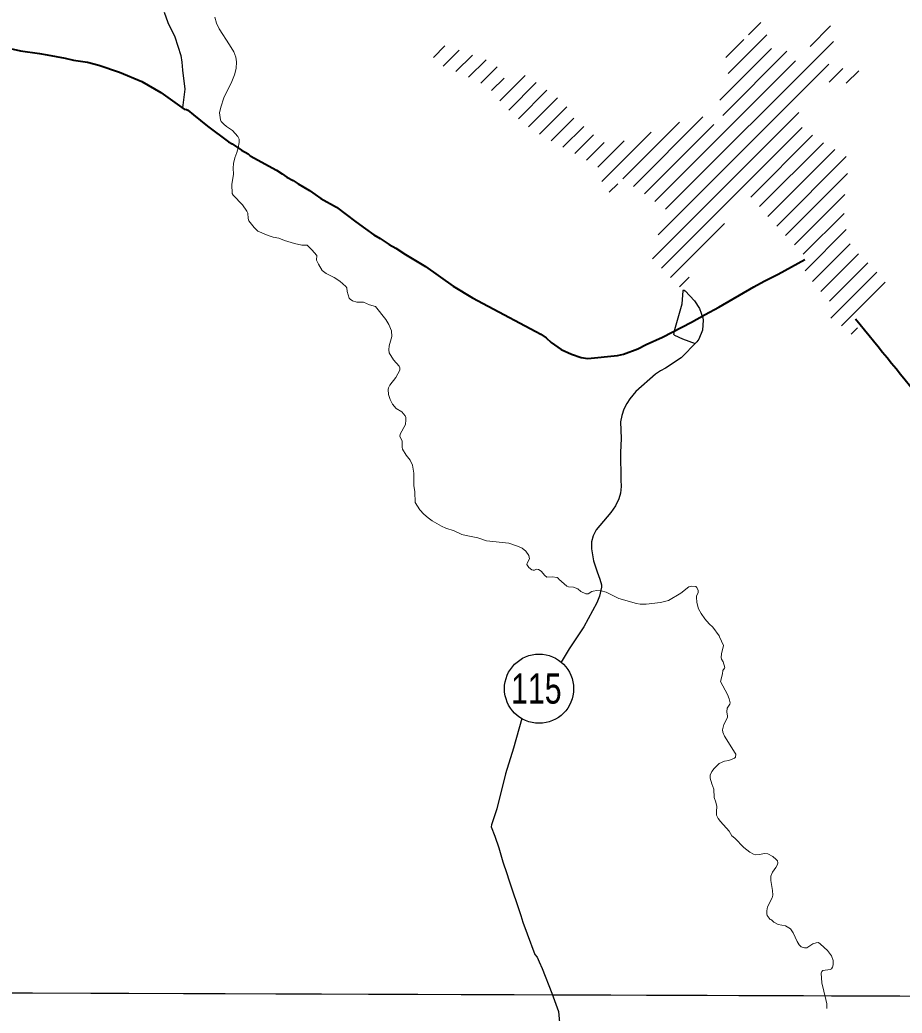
# Model space of a CAD drawing. Extents: x 553962 to 842807, y 8883888 to 9032388.
# Drawn here: x 614032 to 616080, y 8909821 to 8912126 of the extents above; entities that cross this region are included whole.
import ezdxf
from ezdxf.enums import TextEntityAlignment as Align

# ---------------------------------------------------------------- set-up
doc = ezdxf.new("R2010")
doc.units = 0
doc.header["$LTSCALE"] = 200
doc.layers.add('6', color=7, linetype='Continuous', lineweight=13)

msp = doc.modelspace()

# ---------------------------------------------------------------- linework, layer by layer
at = {"layer": '6'}
for p, q in [((615723.1, 8912091.6), (615751.6, 8912120.1)), ((615866.2, 8912064.9), (615913.5, 8912112.3)), ((615530.8, 8911687.2), (615920.2, 8912076.6)), ((615670.7, 8912039.2), (615712.3, 8912080.8)), ((615675.8, 8912001.9), (615765.9, 8912092)), ((614991.9, 8912039.2), (615018.6, 8912065.9)), ((615014.2, 8912019), (615051.5, 8912056.4)), ((615656.6, 8911940.3), (615776.4, 8912060.1)), ((615663.6, 8911904.8), (615812.3, 8912053.5)), ((615043.8, 8912006.3), (615082.5, 8912044.9)), ((615073.5, 8911993.6), (615114.1, 8912034.1)), ((615506.2, 8911705), (615832.4, 8912031.2)), ((615102.3, 8911979.9), (615140.1, 8912017.8)), ((615513.3, 8911627.3), (615909.8, 8912023.7)), ((615910.3, 8911981.8), (615942, 8912013.5)), ((615950.2, 8911979.3), (615979.5, 8912008.6)), ((615127, 8911962.2), (615156.3, 8911991.4)), ((615145.9, 8911938.7), (615204.6, 8911997.4)), ((615166.7, 8911917), (615230.7, 8911981)), ((615189.2, 8911897.1), (615255.5, 8911963.4)), ((615213, 8911878.5), (615280.3, 8911945.8)), ((615238.2, 8911861.3), (615301.4, 8911924.5)), ((615500.3, 8911571.8), (615839.7, 8911911.2)), ((615265.1, 8911845.7), (615317.8, 8911898.4)), ((615431.6, 8911757.6), (615562.9, 8911888.9)), ((615456.2, 8911739.8), (615617.5, 8911901.2)), ((615292.7, 8911830.9), (615340.7, 8911878.9)), ((615382.8, 8911751.2), (615497.4, 8911865.9)), ((615481.7, 8911722.9), (615642.7, 8911883.9)), ((615521.1, 8911550.2), (615847.5, 8911876.6)), ((615320.2, 8911816), (615363.8, 8911859.6)), ((615347.4, 8911800.8), (615388.4, 8911841.7)), ((615373.7, 8911784.6), (615434.8, 8911845.7)), ((615728.4, 8911715.1), (615872.1, 8911858.8)), ((615748.9, 8911693.2), (615897, 8911841.2)), ((615768.1, 8911669.9), (615923.5, 8911825.3)), ((615788.8, 8911648.1), (615950.1, 8911809.5)), ((615809.4, 8911626.3), (615953.2, 8911770.2)), ((615400.2, 8911726.3), (615420.1, 8911746.2)), ((615830, 8911604.6), (615946.5, 8911721.1)), ((615850.5, 8911582.5), (615945.5, 8911677.5)), ((615541.9, 8911528.6), (615667.5, 8911654.2)), ((615854.5, 8911544.2), (615950.1, 8911639.7)), ((615872.1, 8911519.3), (615959.2, 8911606.5)), ((615891.5, 8911496.3), (615978.4, 8911583.2)), ((615911.6, 8911474), (616000, 8911562.4)), ((615914.5, 8911434.4), (616020.8, 8911540.8)), ((615562.9, 8911507.2), (615585.5, 8911529.7)), ((615938.9, 8911416.4), (616040.5, 8911518)), ((615961.7, 8911396.8), (615976.5, 8911411.6)), ((574653.9, 8910009.3), (626625.7, 8909822.1))]:
    msp.add_line(p, q, dxfattribs=at)
at = {"layer": '6', "lineweight": 25}
msp.add_line((615138.8, 8910295.4), (615126.6, 8910258.3), dxfattribs=at)
for points in [[(614367, 8912144.3), (614375.3, 8912120.7), (614391.5, 8912087.1), (614405.8, 8912044.1), (614407.9, 8912028.6), (614409.2, 8912009.7), (614415.2, 8911965.8), (614409.2, 8911922.5)], [(615599.9, 8911375), (615570.6, 8911385.8), (615552.6, 8911394.1), (615550.1, 8911396.3), (615552, 8911408.1), (615569.5, 8911467.6), (615571.8, 8911497.7), (615572.6, 8911500), (615576.1, 8911497.3), (615598, 8911474.4), (615609.3, 8911456.9), (615617.4, 8911434.8), (615618, 8911429.4), (615616.8, 8911406.4), (615607.9, 8911385.5), (615603.3, 8911379.1), (615567.2, 8911342.2), (615530.8, 8911318.5), (615518.9, 8911311.9), (615507.1, 8911303.9), (615461.7, 8911264.1), (615448.1, 8911247.4), (615440.7, 8911235.9), (615434.2, 8911222.9), (615429.1, 8911208.4), (615426.1, 8911193.8), (615427.6, 8911155.1), (615426.4, 8911122.4), (615426.8, 8911058.8), (615427.6, 8911043.4), (615425.9, 8911028), (615422.1, 8911015), (615414.6, 8910998.4), (615403.9, 8910983.4), (615369.6, 8910943.1), (615362.5, 8910929), (615358.7, 8910915.2), (615358.7, 8910898.9), (615363.5, 8910871.4), (615371.8, 8910845.5), (615378.5, 8910828.5), (615382, 8910815.5), (615381.8, 8910809.8), (615377.1, 8910788.9), (615371.3, 8910773.5), (615341.2, 8910717.8), (615307.1, 8910666.5), (615288.4, 8910636.1)], [(615196.8, 8910504.9), (615177.9, 8910436.4), (615158.9, 8910377.1), (615138.8, 8910295.4)], [(615126.6, 8910258.3), (615125.9, 8910253.6), (615134.7, 8910231.8), (615144, 8910204.7), (615152.8, 8910172.4), (615162.3, 8910145.7), (615166.8, 8910130.4), (615195.1, 8910047.8), (615199.5, 8910032.8), (615209.6, 8910005.2)], [(615209.6, 8910005.2), (615227, 8909957.6), (615232.7, 8909951.5), (615237, 8909940.3), (615244.4, 8909924.9), (615267.1, 8909868.1), (615282, 8909824.9)], [(615282, 8909824.9), (615292.5, 8909716.1), (615320.5, 8909565.2), (615327.5, 8909531.6), (615344.7, 8909497.9), (615365.9, 8909445.9), (615390.2, 8909408.2), (615414.6, 8909376.6), (615454.1, 8909327.6), (615483.5, 8909293.9), (615556.6, 8909207.2), (615624.7, 8909143.6), (615643.3, 8909127.9), (615658.6, 8909118.9)]]:
    msp.add_lwpolyline(points, dxfattribs=at)
at = {"layer": '6'}
for points in [[(614484.5, 8912132.9), (614488.5, 8912118.5), (614494.8, 8912105.6), (614519, 8912068.7), (614528.5, 8912052.3), (614533.6, 8912040.3), (614535.2, 8912029.2), (614534.1, 8912013.9), (614530.5, 8911998.8), (614524.3, 8911983.7), (614505.6, 8911945.2), (614498.3, 8911923.7), (614495.8, 8911911), (614498.1, 8911894.5), (614499.6, 8911890.4), (614505.2, 8911884.2), (614511.7, 8911878.7), (614525.4, 8911869.5), (614537.6, 8911855.5), (614541.2, 8911849.9), (614540.9, 8911842.1), (614539, 8911829.5), (614535.8, 8911818.4), (614530.9, 8911806.4), (614528.1, 8911793), (614527.1, 8911782.7), (614527.6, 8911768.3), (614524, 8911744.5), (614525, 8911723.2), (614527.2, 8911719.7), (614548.6, 8911697.1), (614559.2, 8911682.3), (614561, 8911678.1), (614562.1, 8911665.3), (614563.3, 8911660.1), (614575.8, 8911644.3), (614584.1, 8911636.2)], [(614484.5, 8912132.9), (614488.5, 8912118.5), (614494.8, 8912105.6), (614519, 8912068.7), (614528.5, 8912052.3), (614533.6, 8912040.3), (614535.2, 8912029.2), (614534.1, 8912013.9), (614530.5, 8911998.8), (614524.3, 8911983.7), (614505.6, 8911945.2), (614498.3, 8911923.7), (614495.8, 8911911), (614498.1, 8911894.5), (614499.6, 8911890.4), (614505.2, 8911884.2), (614511.7, 8911878.7), (614525.4, 8911869.5), (614537.6, 8911855.5), (614541.2, 8911849.9), (614540.9, 8911842.1), (614539, 8911829.5), (614535.8, 8911818.4), (614530.9, 8911806.4), (614528.1, 8911793), (614527.1, 8911782.7), (614527.6, 8911768.3), (614524, 8911744.5), (614525, 8911723.2), (614527.2, 8911719.7), (614548.6, 8911697.1), (614559.2, 8911682.3), (614561, 8911678.1), (614562.1, 8911665.3), (614563.3, 8911660.1), (614575.8, 8911644.3), (614584.1, 8911636.2)], [(614584.1, 8911636.2), (614584.1, 8911636.2), (614608.1, 8911626), (614620.1, 8911622.5), (614632.8, 8911620.1), (614646.4, 8911614.5), (614669.5, 8911607.6), (614686.7, 8911603.6), (614699.1, 8911603.5)], [(614584.1, 8911636.2), (614584.1, 8911636.2), (614608.1, 8911626), (614620.1, 8911622.5), (614632.8, 8911620.1), (614646.4, 8911614.5), (614669.5, 8911607.6), (614686.7, 8911603.6), (614699.1, 8911603.5)], [(614699.1, 8911603.5), (614709.6, 8911592.7), (614721, 8911579.5), (614721.7, 8911577.4), (614720.5, 8911571.3), (614720.9, 8911568.5), (614725.2, 8911559.5), (614733.7, 8911545.2), (614743, 8911537.5), (614761.4, 8911528.7), (614774.6, 8911520.4), (614789, 8911508.1), (614790.7, 8911504.8), (614791.9, 8911496.1), (614796.7, 8911480.4), (614798.5, 8911478), (614803.8, 8911474.7), (614814.1, 8911471.6), (614829.7, 8911471.7), (614843.8, 8911465.2), (614857.7, 8911461.5)], [(614699.1, 8911603.5), (614709.6, 8911592.7), (614721, 8911579.5), (614721.7, 8911577.4), (614720.5, 8911571.3), (614720.9, 8911568.5), (614725.2, 8911559.5), (614733.7, 8911545.2), (614743, 8911537.5), (614761.4, 8911528.7), (614774.6, 8911520.4), (614789, 8911508.1), (614790.7, 8911504.8), (614791.9, 8911496.1), (614796.7, 8911480.4), (614798.5, 8911478), (614803.8, 8911474.7), (614814.1, 8911471.6), (614829.7, 8911471.7), (614843.8, 8911465.2), (614857.7, 8911461.5)], [(614857.7, 8911461.5), (614881.8, 8911430.8), (614888.6, 8911419.2), (614894.8, 8911405.2)], [(614857.7, 8911461.5), (614881.8, 8911430.8), (614888.6, 8911419.2), (614894.8, 8911405.2)], [(614894.8, 8911405.2), (614895.4, 8911391.4), (614888.9, 8911370.2), (614888.4, 8911360.8), (614889.1, 8911353.8), (614899.5, 8911337.6), (614912.4, 8911323), (614913.7, 8911319.3), (614914.2, 8911313.3), (614904.9, 8911296.6), (614891.1, 8911278.7), (614887.5, 8911272.7), (614886.7, 8911268.4), (614887.5, 8911257.1), (614891.3, 8911245.4), (614896.7, 8911234.7), (614905.3, 8911224.8), (614918.6, 8911216.5), (614926.2, 8911207.2), (614927.8, 8911204), (614928.2, 8911197.9), (614926.8, 8911187.5), (614914.6, 8911165.4), (614913.8, 8911159.4), (614919.2, 8911149.3), (614919.5, 8911135.1), (614920.4, 8911130.5), (614928.7, 8911116), (614938, 8911104.3), (614943.4, 8911093.3), (614946.1, 8911074.3), (614946.5, 8911046), (614948.7, 8911031.5), (614949.6, 8911006.3), (614960.5, 8910989.7), (614969.6, 8910979.2), (614979.4, 8910970.7), (614988.7, 8910963.9), (615010.6, 8910951.4), (615020.6, 8910946.9), (615040, 8910940.5), (615058, 8910932.4), (615068.1, 8910929.7), (615094.7, 8910924.8), (615114.8, 8910917.8), (615166.8, 8910911.8), (615187.2, 8910905), (615197.9, 8910900.2), (615206.5, 8910893.3), (615213.6, 8910883.4), (615215, 8910876), (615209.8, 8910865.4), (615209.1, 8910862.7), (615213.4, 8910855.6), (615220.2, 8910850.1), (615223.2, 8910849.3), (615226.8, 8910849.7), (615230.9, 8910851.5), (615235.7, 8910851.1), (615242.4, 8910846.7), (615250.7, 8910837.1), (615255.1, 8910833.3), (615267.9, 8910833.6), (615278.9, 8910832), (615282.1, 8910830.2)], [(614894.8, 8911405.2), (614895.4, 8911391.4), (614888.9, 8911370.2), (614888.4, 8911360.8), (614889.1, 8911353.8), (614899.5, 8911337.6), (614912.4, 8911323), (614913.7, 8911319.3), (614914.2, 8911313.3), (614904.9, 8911296.6), (614891.1, 8911278.7), (614887.5, 8911272.7), (614886.7, 8911268.4), (614887.5, 8911257.1), (614891.3, 8911245.4), (614896.7, 8911234.7), (614905.3, 8911224.8), (614918.6, 8911216.5), (614926.2, 8911207.2), (614927.8, 8911204), (614928.2, 8911197.9), (614926.8, 8911187.5), (614914.6, 8911165.4), (614913.8, 8911159.4), (614919.2, 8911149.3), (614919.5, 8911135.1), (614920.4, 8911130.5), (614928.7, 8911116), (614938, 8911104.3), (614943.4, 8911093.3), (614946.1, 8911074.3), (614946.5, 8911046), (614948.7, 8911031.5), (614949.6, 8911006.3), (614960.5, 8910989.7), (614969.6, 8910979.2), (614979.4, 8910970.7), (614988.7, 8910963.9), (615010.6, 8910951.4), (615020.6, 8910946.9), (615040, 8910940.5), (615058, 8910932.4), (615068.1, 8910929.7), (615094.7, 8910924.8), (615114.8, 8910917.8), (615166.8, 8910911.8), (615187.2, 8910905), (615197.9, 8910900.2), (615206.5, 8910893.3), (615213.6, 8910883.4), (615215, 8910876), (615209.8, 8910865.4), (615209.1, 8910862.7), (615213.4, 8910855.6), (615220.2, 8910850.1), (615223.2, 8910849.3), (615226.8, 8910849.7), (615230.9, 8910851.5), (615235.7, 8910851.1), (615242.4, 8910846.7), (615250.7, 8910837.1), (615255.1, 8910833.3), (615267.9, 8910833.6), (615278.9, 8910832), (615282.1, 8910830.2)], [(615282.1, 8910830.2), (615283.3, 8910828.4), (615301.8, 8910812), (615305.6, 8910810.9), (615317.4, 8910809.9), (615327, 8910806.2), (615334.1, 8910800.2), (615345.7, 8910794.2), (615350.8, 8910794.5), (615359.4, 8910799.7), (615362.8, 8910800.9), (615370.9, 8910802.2), (615381.1, 8910801.7), (615392.8, 8910798.4), (615422.1, 8910783.9), (615463.6, 8910771.7), (615471.6, 8910770.6), (615485.6, 8910770.5), (615518.7, 8910774.5), (615528.2, 8910776.4), (615537.8, 8910779.3), (615566.4, 8910796.3), (615584.6, 8910810.5), (615590.8, 8910812.2), (615600.7, 8910811.2), (615603.2, 8910808.9), (615606.8, 8910802), (615606.7, 8910796.5), (615602.9, 8910789.8), (615602.2, 8910786.7), (615603.2, 8910774.1), (615607.3, 8910759.9), (615613.3, 8910748.7), (615621.7, 8910736.7), (615632.2, 8910724.8), (615640.6, 8910717.5), (615655, 8910696.9)], [(615282.1, 8910830.2), (615283.3, 8910828.4), (615301.8, 8910812), (615305.6, 8910810.9), (615317.4, 8910809.9), (615327, 8910806.2), (615334.1, 8910800.2), (615345.7, 8910794.2), (615350.8, 8910794.5), (615359.4, 8910799.7), (615362.8, 8910800.9), (615370.9, 8910802.2), (615381.1, 8910801.7), (615392.8, 8910798.4), (615422.1, 8910783.9), (615463.6, 8910771.7), (615471.6, 8910770.6), (615485.6, 8910770.5), (615518.7, 8910774.5), (615528.2, 8910776.4), (615537.8, 8910779.3), (615566.4, 8910796.3), (615584.6, 8910810.5), (615590.8, 8910812.2), (615600.7, 8910811.2), (615603.2, 8910808.9), (615606.8, 8910802), (615606.7, 8910796.5), (615602.9, 8910789.8), (615602.2, 8910786.7), (615603.2, 8910774.1), (615607.3, 8910759.9), (615613.3, 8910748.7), (615621.7, 8910736.7), (615632.2, 8910724.8), (615640.6, 8910717.5), (615655, 8910696.9)], [(615655, 8910696.9), (615656, 8910695), (615665, 8910674.5), (615660.6, 8910655.1), (615659.8, 8910646.5), (615660.9, 8910642.9), (615664.4, 8910636.8), (615668, 8910623.7), (615667.6, 8910622), (615664, 8910616.7), (615663.2, 8910608.5), (615658, 8910591.3), (615674.8, 8910560.7), (615678.6, 8910550.5), (615680.5, 8910541.2), (615679.6, 8910538.6), (615673.4, 8910528.9), (615673.3, 8910520.8), (615674.8, 8910510.7), (615674.5, 8910507.1), (615665.9, 8910491.1), (615662.8, 8910478.6), (615664, 8910473.1), (615667.5, 8910464.5), (615692.6, 8910424.9), (615693.7, 8910422.2), (615692.8, 8910415.3), (615690.4, 8910413.3), (615677.6, 8910408), (615667.7, 8910405.9), (615654.9, 8910400.8), (615643.2, 8910389.5), (615638, 8910382.3), (615634.6, 8910373.3), (615634, 8910366.5), (615637.8, 8910353.2), (615642.9, 8910341.4), (615643.7, 8910321.8), (615647.4, 8910310.9), (615649.7, 8910301.3), (615648.6, 8910289.1), (615649.3, 8910280.6), (615652.9, 8910273.4), (615657.9, 8910266.5), (615678, 8910244), (615684.8, 8910233.2), (615691.8, 8910227.6), (615712.5, 8910205.7), (615726.4, 8910195.1), (615735.1, 8910190.5), (615740.5, 8910189), (615748.6, 8910189.6), (615760.2, 8910191.7), (615768.2, 8910191.4), (615779.6, 8910185.2), (615787.6, 8910178.1), (615790.3, 8910174.6), (615791.2, 8910169.9), (615790.2, 8910166.1), (615787, 8910159.5), (615778.9, 8910148.9), (615775.1, 8910139), (615775.4, 8910128.9), (615779, 8910106.3), (615779.6, 8910095.5)], [(615655, 8910696.9), (615656, 8910695), (615665, 8910674.5), (615660.6, 8910655.1), (615659.8, 8910646.5), (615660.9, 8910642.9), (615664.4, 8910636.8), (615668, 8910623.7), (615667.6, 8910622), (615664, 8910616.7), (615663.2, 8910608.5), (615658, 8910591.3), (615674.8, 8910560.7), (615678.6, 8910550.5), (615680.5, 8910541.2), (615679.6, 8910538.6), (615673.4, 8910528.9), (615673.3, 8910520.8), (615674.8, 8910510.7), (615674.5, 8910507.1), (615665.9, 8910491.1), (615662.8, 8910478.6), (615664, 8910473.1), (615667.5, 8910464.5), (615692.6, 8910424.9), (615693.7, 8910422.2), (615692.8, 8910415.3), (615690.4, 8910413.3), (615677.6, 8910408), (615667.7, 8910405.9), (615654.9, 8910400.8), (615643.2, 8910389.5), (615638, 8910382.3), (615634.6, 8910373.3), (615634, 8910366.5), (615637.8, 8910353.2), (615642.9, 8910341.4), (615643.7, 8910321.8), (615647.4, 8910310.9), (615649.7, 8910301.3), (615648.6, 8910289.1), (615649.3, 8910280.6), (615652.9, 8910273.4), (615657.9, 8910266.5), (615678, 8910244), (615684.8, 8910233.2), (615691.8, 8910227.6), (615712.5, 8910205.7), (615726.4, 8910195.1), (615735.1, 8910190.5), (615740.5, 8910189), (615748.6, 8910189.6), (615760.2, 8910191.7), (615768.2, 8910191.4), (615779.6, 8910185.2), (615787.6, 8910178.1), (615790.3, 8910174.6), (615791.2, 8910169.9), (615790.2, 8910166.1), (615787, 8910159.5), (615778.9, 8910148.9), (615775.1, 8910139), (615775.4, 8910128.9), (615779, 8910106.3), (615779.6, 8910095.5)], [(615779.6, 8910095.5), (615777.8, 8910089), (615767.1, 8910068), (615765.5, 8910058.6), (615765.6, 8910051.5), (615766.8, 8910047.7), (615773.9, 8910038.9), (615776.6, 8910037.6), (615782, 8910032.8), (615792.4, 8910027.4), (615808.9, 8910024.1), (615821.1, 8910017.4), (615827.3, 8910008), (615836, 8909987.3), (615840.8, 8909979.7), (615845.5, 8909975.1), (615853.4, 8909973.2), (615858.7, 8909973.1)], [(615779.6, 8910095.5), (615777.8, 8910089), (615767.1, 8910068), (615765.5, 8910058.6), (615765.6, 8910051.5), (615766.8, 8910047.7), (615773.9, 8910038.9), (615776.6, 8910037.6), (615782, 8910032.8), (615792.4, 8910027.4), (615808.9, 8910024.1), (615821.1, 8910017.4), (615827.3, 8910008), (615836, 8909987.3), (615840.8, 8909979.7), (615845.5, 8909975.1), (615853.4, 8909973.2), (615858.7, 8909973.1)], [(615858.7, 8909973.1), (615872.3, 8909982.2), (615872.3, 8909982.2), (615880.5, 8909984.9), (615885.6, 8909985), (615890.5, 8909981.6), (615906.4, 8909966.9), (615915.9, 8909954.7), (615919.4, 8909943.5), (615920.1, 8909933.2), (615918.5, 8909928), (615915.6, 8909924.2), (615912.6, 8909922.4), (615895.5, 8909920.7), (615893.3, 8909918.3), (615891.8, 8909914.3), (615893.8, 8909891.8), (615903, 8909853.2), (615904.8, 8909843), (615905.3, 8909832)], [(615858.7, 8909973.1), (615872.3, 8909982.2), (615872.3, 8909982.2), (615880.5, 8909984.9), (615885.6, 8909985), (615890.5, 8909981.6), (615906.4, 8909966.9), (615915.9, 8909954.7), (615919.4, 8909943.5), (615920.1, 8909933.2), (615918.5, 8909928), (615915.6, 8909924.2), (615912.6, 8909922.4), (615895.5, 8909920.7), (615893.3, 8909918.3), (615891.8, 8909914.3), (615893.8, 8909891.8), (615903, 8909853.2), (615904.8, 8909843), (615905.3, 8909832)]]:
    msp.add_lwpolyline(points, dxfattribs=at)
at = {"layer": '6', "lineweight": 40}
for points in [[(614002.3, 8912061.8), (614033.2, 8912054.9), (614077.8, 8912048.2), (614095.5, 8912045.1)], [(614095.5, 8912045.1), (614137.1, 8912037.7), (614156.6, 8912033.3), (614189.2, 8912028.5), (614215.5, 8912021.7), (614263.5, 8912005.4), (614314.9, 8911983.3), (614359.3, 8911958.1), (614413.5, 8911919.6), (614418.7, 8911918.6), (614421.7, 8911917.2), (614435.2, 8911906.1)], [(614435.2, 8911906.1), (614467.8, 8911879.5), (614516.5, 8911843.4), (614525, 8911838.5), (614546.8, 8911823.9), (614561.7, 8911815.5), (614566.3, 8911811.2), (614628, 8911777.5), (614641.1, 8911769.4), (614651.5, 8911761.7), (614666.3, 8911753.9), (614677.9, 8911746.1), (614704.5, 8911730.6), (614730.4, 8911712.3), (614767.2, 8911691.7), (614812.1, 8911658)], [(614812.1, 8911658), (614834.3, 8911641.2), (614853.5, 8911627.7), (614868.4, 8911619.3), (614889.4, 8911605.2), (614904.7, 8911597), (614927.5, 8911582), (614973.7, 8911554), (615037.8, 8911508.7), (615082.7, 8911481.4), (615119.3, 8911462), (615230, 8911403.5)], [(615622.9, 8911442.5), (615654.7, 8911459.9), (615735.5, 8911507.1), (615759.3, 8911519.9), (615791.8, 8911536), (615853.7, 8911570.5)], [(615230, 8911403.5), (615241.5, 8911397.4), (615253.3, 8911388.6), (615265.3, 8911377.7), (615288.5, 8911361.6), (615312.4, 8911350.8), (615334.8, 8911342.9), (615350.2, 8911341), (615419.2, 8911347.2), (615433.5, 8911350.8), (615466.3, 8911362.9), (615486, 8911373.3), (615523.5, 8911390.4), (615590.8, 8911424.9), (615622.9, 8911442.5)]]:
    msp.add_lwpolyline(points, dxfattribs=at)
at = {"layer": '6'}
msp.add_lwpolyline([(618535.2, 8909853.3), (607574.3, 8909890.7), (607543.3, 8898835.3), (618504.2, 8898795.8)], close=True, dxfattribs=at)
at = {"layer": '6', "lineweight": 25}
msp.add_circle((615237.1, 8910574.3), 80.3, dxfattribs=at)
at = {"layer": '6', "lineweight": 40}
msp.add_spline([(615971.7, 8911432.5), (616138.5, 8911227.2), (616313.3, 8911009), (616504.8, 8910771.9), (616895.5, 8910293.3), (617079.2, 8910062.8), (617725.5, 8909265.3), (618056.1, 8908857.7), (618263.2, 8908603.7), (618306.6, 8908556.9), (618336.6, 8908483.4), (618463.5, 8908212.8), (618533.7, 8908055.7), (618557.1, 8908012.3), (618590.5, 8907985.6), (618640.6, 8907962.2), (618764.1, 8907925.4), (618847.6, 8907882), (618877.7, 8907865.3), (618937.8, 8907811.8), (618997.9, 8907778.4), (619028, 8907745), (619141.5, 8907698.2), (619241.7, 8907674.8), (619372, 8907724.9), (619488.8, 8907801.8), (619552.3, 8907878.6), (619575.7, 8907905.4), (619599.1, 8907898.7), (619632.5, 8907871.9), (619679.2, 8907871.9), (619782.8, 8907918.7), (619872.9, 8907952.1), (619949.7, 8907952.1), (620026.6, 8907932.1), (620080, 8907908.7), (620120.1, 8907902), (620166.8, 8907932.1), (620233.6, 8907952.1), (620300.4, 8907958.8), (620363.9, 8907992.2), (620444, 8908052.4), (620517.5, 8908095.8), (620586.9, 8908115.3)], degree=3, dxfattribs=at)

# ---------------------------------------------------------------- texts
at = {"layer": '6', "width": 0.75}
msp.add_text('115', height=70, dxfattribs=at).set_placement((615230.8, 8910539.7), align=Align.CENTER)

doc.saveas('drawing.dxf')
